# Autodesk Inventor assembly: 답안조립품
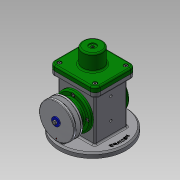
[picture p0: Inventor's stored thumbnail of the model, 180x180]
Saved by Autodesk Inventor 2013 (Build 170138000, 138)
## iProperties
Created: 2019-08
Part Number: 답안조립품
Document SubType Name: Assembly
Designer: Administrator
Author: Administrator
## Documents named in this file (18)
- C:\Documents and Settings\Administrator\바탕 화면\490804V1012\답안조립품.iam
- C:\Documents and Settings\Administrator\바탕 화면\490804V1012\본체.ipt
- C:\Documents and Settings\Administrator\바탕 화면\490804V1012\편심축.ipt
- C:\Documents and Settings\Administrator\바탕 화면\490804V1012\베어링 17 x 40 x 12.ipt
- C:\Documents and Settings\Administrator\바탕 화면\490804V1012\뒤커버.ipt
- C:\Documents and Settings\Administrator\바탕 화면\490804V1012\볼트 M4 x 8.ipt
- C:\Documents and Settings\Administrator\바탕 화면\490804V1012\앞커버.ipt
- C:\Documents and Settings\Administrator\바탕 화면\490804V1012\오일 실 17 30 8.ipt
- C:\Documents and Settings\Administrator\바탕 화면\490804V1012\키 4 x 4 x 12.ipt
- C:\Documents and Settings\Administrator\바탕 화면\490804V1012\V-벨트풀리.ipt
- C:\Documents and Settings\Administrator\바탕 화면\490804V1012\와셔 4x16.ipt
- C:\Documents and Settings\Administrator\바탕 화면\490804V1012\볼트 M4 x 10.ipt
- C:\Documents and Settings\Administrator\바탕 화면\490804V1012\링크.ipt
- C:\Documents and Settings\Administrator\바탕 화면\490804V1012\클레비스 핀 6 x 22.ipt
- 클레비스 핀 6 x 22.ipt
- C:\Documents and Settings\Administrator\바탕 화면\490804V1012\슬라이더.ipt
- C:\Documents and Settings\Administrator\바탕 화면\490804V1012\덮개.ipt
- C:\Documents and Settings\Administrator\바탕 화면\490804V1012\E-링.ipt
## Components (2 placed, 2 different names)
1. V-벨트풀리:1
2. E-링:1
## Component patterns: 구성요소 패턴 3:2 (2 elements)
